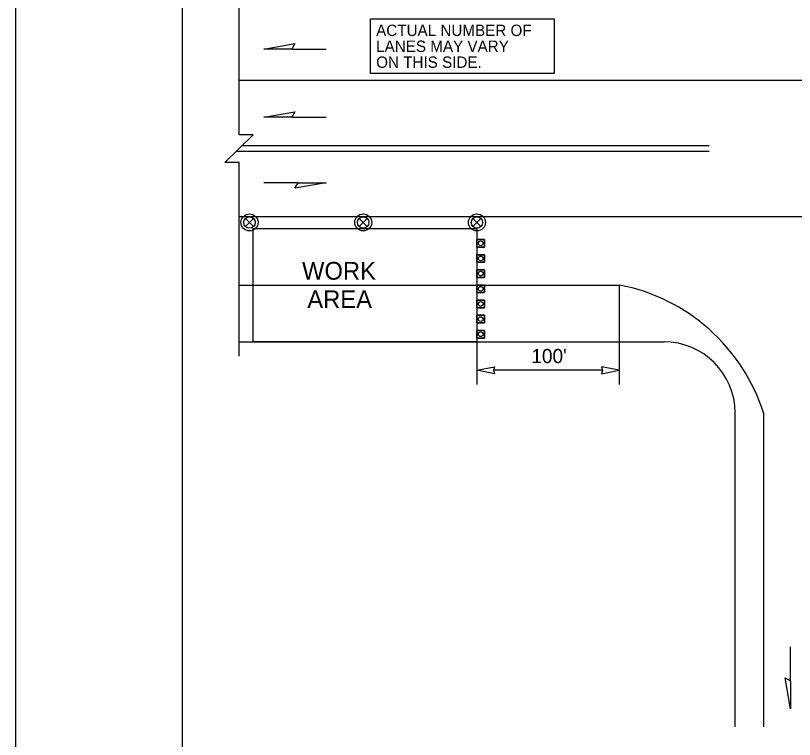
# Model space of a CAD drawing. Extents: x 99958 to 100176, y 99935 to 100011.
# Drawn here: x 100039.062 to 100043.446, y 100001.834 to 100005.909 of the extents above; entities that cross this region are included whole.
import ezdxf

# ---------------------------------------------------------------- set-up
doc = ezdxf.new("R2010")
doc.units = 0
for name, color, linetype in [('RD_ED_ShoulderPavedEdge', 7, 'Continuous'), ('RD_MK_LineDblYellowCenter', 7, 'Continuous'), ('RD_MK_LineEdgeWhite', 7, 'Continuous'), ('RD_MK_LineEdgeYellow', 7, 'Continuous'), ('RD_MK_LineLane', 7, 'Continuous'), ('SH_GI_PlotLimits', 7, 'Continuous'), ('SH_GI_SheetBorder', 7, 'Continuous'), ('SH_TI_Tables', 7, 'Continuous'), ('TR_WZ_TrafficCone', 7, 'Continuous'), ('TR_WZ_TrafficSafetyDrum', 7, 'Continuous'), ('TR_WZ_WorkAreaLabel', 7, 'Continuous'), ('TR_WZ_WorkZoneDetails', 7, 'Continuous'), ('TR_WZ_WorkZoneTextCurrent', 7, 'Continuous')]:
    doc.layers.add(name, color=color, linetype=linetype)

msp = doc.modelspace()

# ---------------------------------------------------------------- linework, layer by layer
at = {"layer": 'RD_ED_ShoulderPavedEdge'}
msp.add_line((100040.32, 100004.0725), (100042.7119, 100004.0725), dxfattribs=at)
msp.add_lwpolyline([(100043.1119, 100001.9059), (100043.1119, 100003.6724)], dxfattribs=at)
msp.add_arc((100042.7119, 100003.6724), 0.4, 0, 90, dxfattribs=at)
at = {"layer": 'RD_MK_LineDblYellowCenter'}
for p, q in [((100042.9653, 100005.1445), (100040.3035, 100005.1445)), ((100042.9653, 100005.1765), (100040.3365, 100005.1765))]:
    msp.add_line(p, q, dxfattribs=at)
at = {"layer": 'RD_MK_LineEdgeWhite'}
msp.add_line((100043.2719, 100003.6724), (100043.2719, 100001.9059), dxfattribs=at)
msp.add_arc((100042.257, 100003.3462), 1.0661, 17.8172, 78.9158, dxfattribs=at)
at = {"layer": 'RD_MK_LineEdgeYellow'}
msp.add_line((100040.32, 100004.3924), (100042.4619, 100004.3924), dxfattribs=at)
at = {"layer": 'RD_MK_LineLane'}
for points in [[(100047.555, 100005.5445), (100040.32, 100005.5445)], [(100047.555, 100004.7765), (100040.32, 100004.7765)]]:
    msp.add_lwpolyline(points, dxfattribs=at)
at = {"layer": 'SH_GI_PlotLimits'}
msp.add_lwpolyline([(100039.0625, 99999.6875), (100056.0625, 99999.6875), (100056.0625, 100010.6875), (100039.0625, 100010.6875)], close=True, dxfattribs=at)
at = {"layer": 'SH_GI_SheetBorder'}
msp.add_line((100040, 100010.375), (100040, 100000), dxfattribs=at)
at = {"layer": 'SH_TI_Tables'}
msp.add_lwpolyline([(100041.0598, 100005.8901), (100042.0943, 100005.8901), (100042.0943, 100005.5831), (100041.0598, 100005.5831)], close=True, dxfattribs=at)
at = {"layer": 'TR_WZ_TrafficCone'}
for points in [[(100041.7016, 100004.6485), (100041.7016, 100004.6058), (100041.6589, 100004.6058), (100041.6589, 100004.6485), (100041.7016, 100004.6485)], [(100041.6589, 100004.6485), (100041.6589, 100004.6058), (100041.7016, 100004.6058), (100041.7016, 100004.6485), (100041.6589, 100004.6485)], [(100041.7016, 100004.5631), (100041.7016, 100004.5205), (100041.6589, 100004.5205), (100041.6589, 100004.5631), (100041.7016, 100004.5631)], [(100041.6589, 100004.5631), (100041.6589, 100004.5205), (100041.7016, 100004.5205), (100041.7016, 100004.5631), (100041.6589, 100004.5631)], [(100041.7016, 100004.4778), (100041.7016, 100004.4351), (100041.6589, 100004.4351), (100041.6589, 100004.4778), (100041.7016, 100004.4778)], [(100041.6589, 100004.4778), (100041.6589, 100004.4351), (100041.7016, 100004.4351), (100041.7016, 100004.4778), (100041.6589, 100004.4778)], [(100041.7016, 100004.3924), (100041.7016, 100004.3498), (100041.6589, 100004.3498), (100041.6589, 100004.3924), (100041.7016, 100004.3924)], [(100041.6589, 100004.3924), (100041.6589, 100004.3498), (100041.7016, 100004.3498), (100041.7016, 100004.3924), (100041.6589, 100004.3924)], [(100041.7016, 100004.3071), (100041.7016, 100004.2644), (100041.6589, 100004.2644), (100041.6589, 100004.3071), (100041.7016, 100004.3071)], [(100041.6589, 100004.3071), (100041.6589, 100004.2644), (100041.7016, 100004.2644), (100041.7016, 100004.3071), (100041.6589, 100004.3071)], [(100041.7016, 100004.2218), (100041.7016, 100004.1791), (100041.6589, 100004.1791), (100041.6589, 100004.2218), (100041.7016, 100004.2218)], [(100041.6589, 100004.2218), (100041.6589, 100004.1791), (100041.7016, 100004.1791), (100041.7016, 100004.2218), (100041.6589, 100004.2218)], [(100041.7016, 100004.1364), (100041.7016, 100004.0938), (100041.6589, 100004.0938), (100041.6589, 100004.1364), (100041.7016, 100004.1364)], [(100041.6589, 100004.1364), (100041.6589, 100004.0938), (100041.7016, 100004.0938), (100041.7016, 100004.1364), (100041.6589, 100004.1364)]]:
    msp.add_lwpolyline(points, dxfattribs=at)
for centre in [(100041.6803, 100004.6271), (100041.6803, 100004.5418), (100041.6803, 100004.4565), (100041.6803, 100004.3711), (100041.6803, 100004.2858), (100041.6803, 100004.2004), (100041.6803, 100004.1151)]:
    msp.add_circle(centre, 0.0133, dxfattribs=at)
at = {"layer": 'TR_WZ_TrafficSafetyDrum'}
for p, q in [((100040.3563, 100004.7671), (100040.4015, 100004.7218)), ((100040.4015, 100004.7671), (100040.3563, 100004.7218)), ((100040.9963, 100004.7671), (100041.0415, 100004.7218)), ((100041.0415, 100004.7671), (100040.9963, 100004.7218)), ((100041.6363, 100004.7671), (100041.6815, 100004.7218)), ((100041.6815, 100004.7671), (100041.6363, 100004.7218))]:
    msp.add_line(p, q, dxfattribs=at)
for centre, radius in [((100040.3789, 100004.7445), 0.048), ((100040.3789, 100004.7445), 0.048), ((100041.0189, 100004.7445), 0.048), ((100041.0189, 100004.7445), 0.048), ((100041.6589, 100004.7445), 0.048), ((100041.6589, 100004.7445), 0.048), ((100040.3789, 100004.7445), 0.032), ((100041.0189, 100004.7445), 0.032), ((100041.6589, 100004.7445), 0.032)]:
    msp.add_circle(centre, radius, dxfattribs=at)
at = {"layer": 'TR_WZ_WorkZoneDetails'}
for p, q in [((100040.6169, 100005.721), (100040.8098, 100005.721)), ((100040.6169, 100005.337), (100040.8098, 100005.337)), ((100040.6526, 100004.9685), (100040.4597, 100004.9685)), ((100042.4589, 100004.3924), (100042.4589, 100003.8325)), ((100041.6589, 100004.0725), (100041.6589, 100003.8325)), ((100042.3652, 100003.9125), (100041.7526, 100003.9125)), ((100043.4242, 100002.1631), (100043.4242, 100002.356))]:
    msp.add_line(p, q, dxfattribs=at)
msp.add_lwpolyline([(100040.32, 100003.9925), (100040.32, 100005.083), (100040.24, 100005.083), (100040.4, 100005.2379), (100040.32, 100005.2379), (100040.32, 100006.3285)], dxfattribs=at)
for points in [[(100040.4597, 100005.721), (100040.6347, 100005.7519), (100040.6169, 100005.721)], [(100040.4597, 100005.337), (100040.6347, 100005.3679), (100040.6169, 100005.337)], [(100040.8098, 100004.9685), (100040.6347, 100004.9376), (100040.6526, 100004.9685)], [(100040.4, 100004.0725), (100040.4, 100004.7114), (100041.6589, 100004.7114), (100041.6589, 100004.0725)], [(100041.6589, 100003.9125), (100041.7572, 100003.9317), (100041.7526, 100003.9125), (100041.7572, 100003.8932)], [(100042.4589, 100003.9125), (100042.3606, 100003.9317), (100042.3652, 100003.9125), (100042.3606, 100003.8932)], [(100043.4242, 100002.0059), (100043.3933, 100002.181), (100043.4242, 100002.1631)]]:
    msp.add_lwpolyline(points, close=True, dxfattribs=at)

# ---------------------------------------------------------------- texts
at = {"layer": 'SH_TI_Tables'}
for s, p in [('ACTUAL NUMBER OF', (100041.0918, 100005.7941)), ('LANES MAY VARY', (100041.0918, 100005.7045)), ('ON THIS SIDE.', (100041.0918, 100005.6149))]:
    msp.add_text(s, height=0.064, rotation=360, dxfattribs=at).set_placement(p)
at = {"layer": 'TR_WZ_WorkAreaLabel'}
for s, p in [('WORK', (100040.6746, 100004.4225)), ('AREA', (100040.7043, 100004.2624))]:
    msp.add_text(s, height=0.1, dxfattribs=at).set_placement(p)
at = {"layer": 'TR_WZ_WorkZoneTextCurrent'}
msp.add_text("100'", height=0.08, rotation=360, dxfattribs=at).set_placement((100041.9653, 100003.9525))

doc.saveas('drawing.dxf')
